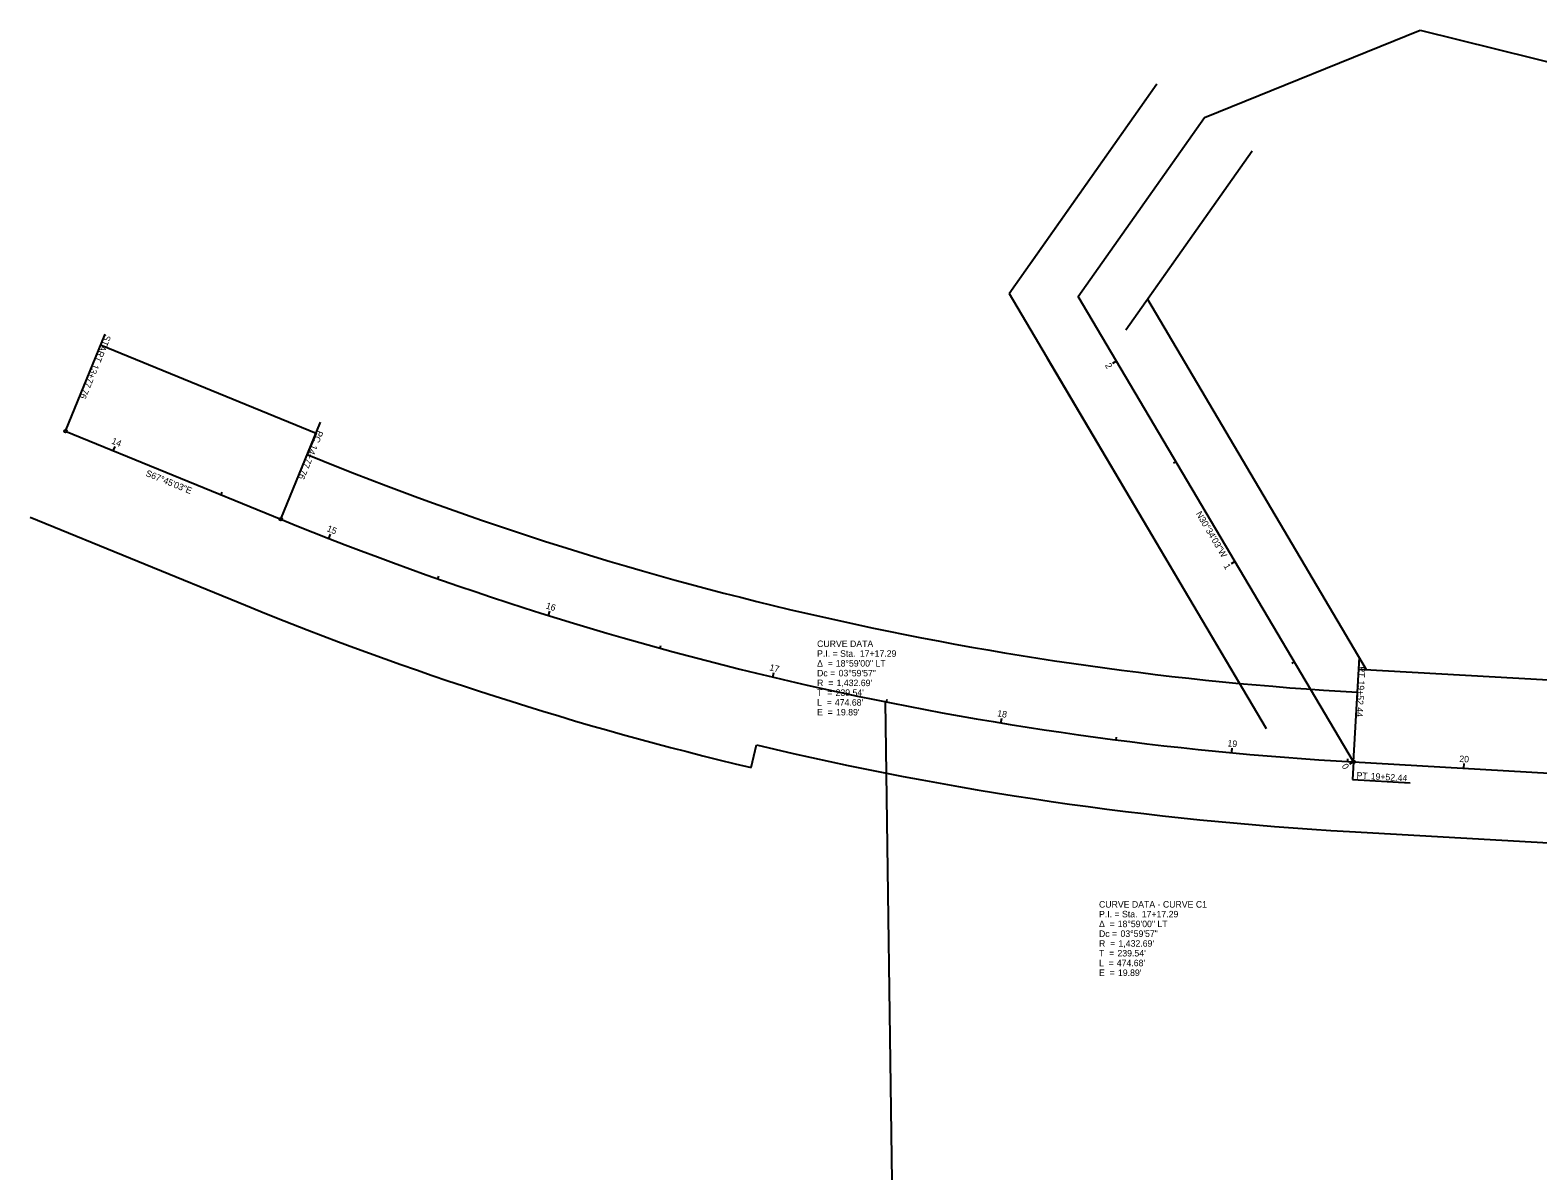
# Model space of a CAD drawing. Extents: x 2273856 to 2278684, y 652916 to 655179.
# Drawn here: x 2273890 to 2274537, y 654538 to 655028 of the extents above; entities that cross this region are included whole.
import ezdxf

# ---------------------------------------------------------------- set-up
doc = ezdxf.new("R2010")
doc.units = 0
for name, color, linetype in [('DV_X_Property_Line', 7, 'Continuous'), ('GE_X_Alignment_100_Stations', 7, 'Continuous'), ('RW_X_CL', 7, 'Continuous'), ('RW_X_CL_1000_Curve_Data', 7, 'Continuous'), ('RW_X_CL_1000_Stations', 7, 'Continuous'), ('RW_X_CL_100_Curve_Data', 7, 'Continuous'), ('RW_X_CL_100_Stations', 7, 'Continuous'), ('RW_X_CL_500_Curve_Data', 7, 'Continuous'), ('RW_X_CL_500_Stations', 7, 'Continuous'), ('RW_X_Esmt_SH', 7, 'Continuous')]:
    doc.layers.add(name, color=color, linetype=linetype)

msp = doc.modelspace()

# ---------------------------------------------------------------- linework, layer by layer
at = {"layer": 'DV_X_Property_Line'}
for p, q in [((2274394.14, 654990.65), (2274486.83, 655028.17)), ((2274486.83, 655028.17), (2274732.19, 654967.18)), ((2274256.97, 654739.46), (2274264.62, 654176.5))]:
    msp.add_line(p, q, dxfattribs=at)
at = {"layer": 'GE_X_Alignment_100_Stations'}
for p, q in [((2274356.41, 654885.81), (2274354.68, 654884.8)), ((2274380.8, 654842.15), (2274381.83, 654842.76)), ((2274407.26, 654799.71), (2274405.54, 654798.69)), ((2274431.66, 654756.05), (2274432.69, 654756.66)), ((2274458.12, 654713.61), (2274456.4, 654712.59))]:
    msp.add_line(p, q, dxfattribs=at)
at = {"layer": 'RW_X_CL'}
for p, q in [((2274339.92, 654913.73), (2274394.14, 654990.65)), ((2274458.12, 654713.61), (2274339.92, 654913.73)), ((2273904.71, 654855.81), (2273997.27, 654817.95)), ((2274458.12, 654713.61), (2274687.5, 654700.52))]:
    msp.add_line(p, q, dxfattribs=at)
msp.add_arc((2274539.73, 656143.97), 1432.69, 247.75095, 266.73428, dxfattribs=at)
at = {"layer": 'RW_X_CL_1000_Stations'}
for p, q in [((2273904.71, 654855.81), (2273921.75, 654897.46)), ((2273997.27, 654817.95), (2274014.31, 654859.6)), ((2274017.92, 654809.69), (2274018.36, 654810.81)), ((2274458.12, 654713.61), (2274460.68, 654758.54)), ((2274505.6, 654710.9), (2274505.72, 654712.9))]:
    msp.add_line(p, q, dxfattribs=at)
for centre in [(2273904.71, 654855.81), (2273997.27, 654817.95), (2274458.12, 654713.61)]:
    msp.add_circle(centre, 0.6, dxfattribs=at)
at = {"layer": 'RW_X_CL_100_Stations'}
for p, q in [((2273904.71, 654855.81), (2273921.75, 654897.46)), ((2273997.27, 654817.95), (2274014.31, 654859.6)), ((2273925.3, 654847.39), (2273926.06, 654849.24)), ((2273971.58, 654828.46), (2273972.03, 654829.57)), ((2274017.92, 654809.69), (2274018.65, 654811.55)), ((2274064.79, 654792.29), (2274065.19, 654793.43)), ((2274112.25, 654776.55), (2274112.84, 654778.45)), ((2274160.22, 654762.46), (2274160.54, 654763.62)), ((2274208.65, 654750.06), (2274209.12, 654752.01)), ((2274257.49, 654739.36), (2274257.73, 654740.53)), ((2274306.67, 654730.36), (2274307, 654732.34)), ((2274356.14, 654723.09), (2274356.29, 654724.28)), ((2274405.83, 654717.55), (2274406.02, 654719.54)), ((2274455.68, 654713.75), (2274455.75, 654714.95)), ((2274458.12, 654713.61), (2274457.68, 654706)), ((2274505.6, 654710.9), (2274505.72, 654712.9)), ((2274457.68, 654706), (2274482.46, 654704.58))]:
    msp.add_line(p, q, dxfattribs=at)
for centre in [(2273904.71, 654855.81), (2273997.27, 654817.95), (2274458.12, 654713.61)]:
    msp.add_circle(centre, 0.6, dxfattribs=at)
at = {"layer": 'RW_X_CL_500_Stations'}
for p, q in [((2273904.71, 654855.81), (2273921.75, 654897.46)), ((2273997.27, 654817.95), (2274014.31, 654859.6)), ((2273925.3, 654847.39), (2273925.76, 654848.5)), ((2274017.92, 654809.69), (2274018.65, 654811.55)), ((2274112.25, 654776.55), (2274112.6, 654777.69)), ((2274458.12, 654713.61), (2274460.68, 654758.54)), ((2274208.65, 654750.06), (2274208.93, 654751.23)), ((2274306.67, 654730.36), (2274306.87, 654731.55)), ((2274405.83, 654717.55), (2274405.94, 654718.75)), ((2274505.6, 654710.9), (2274505.72, 654712.9))]:
    msp.add_line(p, q, dxfattribs=at)
for centre in [(2273904.71, 654855.81), (2273997.27, 654817.95), (2274458.12, 654713.61)]:
    msp.add_circle(centre, 0.6, dxfattribs=at)
at = {"layer": 'RW_X_Esmt_SH'}
for p, q in [((2274310.18, 654914.93), (2274373.71, 655005.05)), ((2274319.49, 654928.13), (2274373.71, 655005.05)), ((2274360.35, 654899.32), (2274414.58, 654976.24)), ((2274369.66, 654912.53), (2274414.58, 654976.24)), ((2274310.18, 654914.93), (2274409.14, 654747.37)), ((2274369.66, 654912.53), (2274463.68, 654753.36)), ((2274369.66, 654912.53), (2274463.68, 654753.36)), ((2273919.86, 654892.84), (2274012.41, 654854.97)), ((2274326.61, 654887.1), (2274420.62, 654727.93)), ((2274012.41, 654854.97), (2274008.63, 654845.72)), ((2273889.57, 654818.79), (2273982.12, 654780.93)), ((2274459.83, 654743.56), (2274460.4, 654753.54)), ((2274460.4, 654753.54), (2274689.78, 654740.45)), ((2274199.4, 654711.15), (2274201.71, 654720.88)), ((2274456.41, 654683.66), (2274685.8, 654670.57))]:
    msp.add_line(p, q, dxfattribs=at)
for radius, start, end in [(1402.69, 247.75095, 266.73428), (1472.69, 247.75095, 256.63836), (1462.69, 256.63836, 266.73428)]:
    msp.add_arc((2274539.73, 656143.97), radius, start, end, dxfattribs=at)

# ---------------------------------------------------------------- texts
at = {"layer": 'GE_X_Alignment_100_Stations'}
for s, p in [('2', (2274351.28, 654884.07)), ('N30°34\'03"W', (2274390.32, 654820.3)), ('1', (2274402.22, 654797.82)), ('0', (2274452.99, 654711.86))]:
    msp.add_text(s, height=2.8, rotation=300.56762, dxfattribs=at).set_placement(p)
at = {"layer": 'RW_X_CL_1000_Curve_Data'}
msp.add_text('S67°45\'03"E', height=2.8, rotation=337.75095, dxfattribs=at).set_placement((2273938.93, 654836.63))
for s, p in [('CURVE DATA', (2274227.69, 654762.98)), ('P.I. = Sta. ', (2274227.69, 654758.78)), ('17+17.29', (2274246.06, 654758.78)), ('Δ  = ', (2274227.69, 654754.58)), ('18°59\'00" LT', (2274235.72, 654754.58)), ('Dc = ', (2274227.69, 654750.38)), ('R  = ', (2274227.69, 654746.18)), ("1,432.69'", (2274236.06, 654746.18)), ('03°59\'57"', (2274236.93, 654750.38)), ('T  = ', (2274227.69, 654741.98)), ("239.54'", (2274235.63, 654741.98)), ('L  = ', (2274227.69, 654737.78)), ('E  = ', (2274227.69, 654733.58)), ("474.68'", (2274235.34, 654737.78)), ("19.89'", (2274235.85, 654733.58))]:
    msp.add_text(s, height=2.8, dxfattribs=at).set_placement(p)
at = {"layer": 'RW_X_CL_1000_Stations'}
for s, rotation, p in [('START', 247.75095, (2273921.8, 654897.45)), ('13+77.76', 247.75095, (2273916.67, 654884.91)), ('PC', 247.75095, (2274013.02, 654856.34)), ('14+77.76', 247.75095, (2274010.55, 654850.3)), ('PT', 266.73428, (2274460.51, 654754.77)), ('19+52.44', 266.73428, (2274460.17, 654748.69)), ('20', 356.73428, (2274503.56, 654713.57))]:
    msp.add_text(s, height=2.8, rotation=rotation, dxfattribs=at).set_placement(p)
at = {"layer": 'RW_X_CL_100_Curve_Data'}
msp.add_text('S67°45\'03"E', height=2.8, rotation=337.75095, dxfattribs=at).set_placement((2273938.93, 654836.63))
msp.add_text('S67°45\'03"E', height=2.8, rotation=337.75095, dxfattribs=at).set_placement((2273938.93, 654836.63))
for s, p in [('CURVE DATA - CURVE C1', (2274348.82, 654650.97)), ('Δ  = ', (2274348.82, 654642.57)), ('P.I. = Sta. ', (2274348.82, 654646.77)), ('18°59\'00" LT', (2274356.84, 654642.57)), ('17+17.29', (2274367.19, 654646.77)), ('Dc = ', (2274348.82, 654638.37)), ('03°59\'57"', (2274358.06, 654638.37)), ('T  = ', (2274348.82, 654629.97)), ('R  = ', (2274348.82, 654634.17)), ("239.54'", (2274356.75, 654629.97)), ("1,432.69'", (2274357.19, 654634.17)), ('L  = ', (2274348.82, 654625.77)), ('E  = ', (2274348.82, 654621.57)), ("474.68'", (2274356.46, 654625.77)), ("19.89'", (2274356.97, 654621.57))]:
    msp.add_text(s, height=2.8, dxfattribs=at).set_placement(p)
at = {"layer": 'RW_X_CL_100_Stations'}
for s, rotation, p in [('START', 247.75095, (2273921.8, 654897.45)), ('13+77.76', 247.75095, (2273916.67, 654884.91)), ('14', 337.75095, (2273924.26, 654850.52)), ('PC', 247.75095, (2274013.02, 654856.34)), ('14+77.76', 247.75095, (2274010.55, 654850.3)), ('15', 338.64045, (2274016.79, 654812.86)), ('16', 342.63962, (2274110.91, 654779.63)), ('17', 346.6388, (2274207.04, 654753.01)), ('18', 350.63797, (2274304.93, 654733.23)), ('19', 354.63715, (2274403.91, 654720.29)), ('20', 356.73428, (2274503.56, 654713.57)), ('PT', 356.73428, (2274459.42, 654706.44)), ('19+52.44', 356.73428, (2274465.5, 654706.1))]:
    msp.add_text(s, height=2.8, rotation=rotation, dxfattribs=at).set_placement(p)
at = {"layer": 'RW_X_CL_500_Curve_Data'}
for s, p in [('CURVE DATA', (2274227.69, 654762.98)), ('P.I. = Sta. ', (2274227.69, 654758.78)), ('17+17.29', (2274246.06, 654758.78)), ('Δ  = ', (2274227.69, 654754.58)), ('18°59\'00" LT', (2274235.72, 654754.58)), ('Dc = ', (2274227.69, 654750.38)), ('R  = ', (2274227.69, 654746.18)), ("1,432.69'", (2274236.06, 654746.18)), ('03°59\'57"', (2274236.93, 654750.38)), ('T  = ', (2274227.69, 654741.98)), ("239.54'", (2274235.63, 654741.98)), ('L  = ', (2274227.69, 654737.78)), ('E  = ', (2274227.69, 654733.58)), ("474.68'", (2274235.34, 654737.78)), ("19.89'", (2274235.85, 654733.58))]:
    msp.add_text(s, height=2.8, dxfattribs=at).set_placement(p)
at = {"layer": 'RW_X_CL_500_Stations'}
for s, rotation, p in [('START', 247.75095, (2273921.8, 654897.45)), ('13+77.76', 247.75095, (2273916.67, 654884.91)), ('PC', 247.75095, (2274013.02, 654856.34)), ('14+77.76', 247.75095, (2274010.55, 654850.3)), ('15', 338.64045, (2274016.79, 654812.86)), ('PT', 266.73428, (2274460.51, 654754.77)), ('19+52.44', 266.73428, (2274460.17, 654748.69)), ('20', 356.73428, (2274503.56, 654713.57))]:
    msp.add_text(s, height=2.8, rotation=rotation, dxfattribs=at).set_placement(p)

doc.saveas('drawing.dxf')
